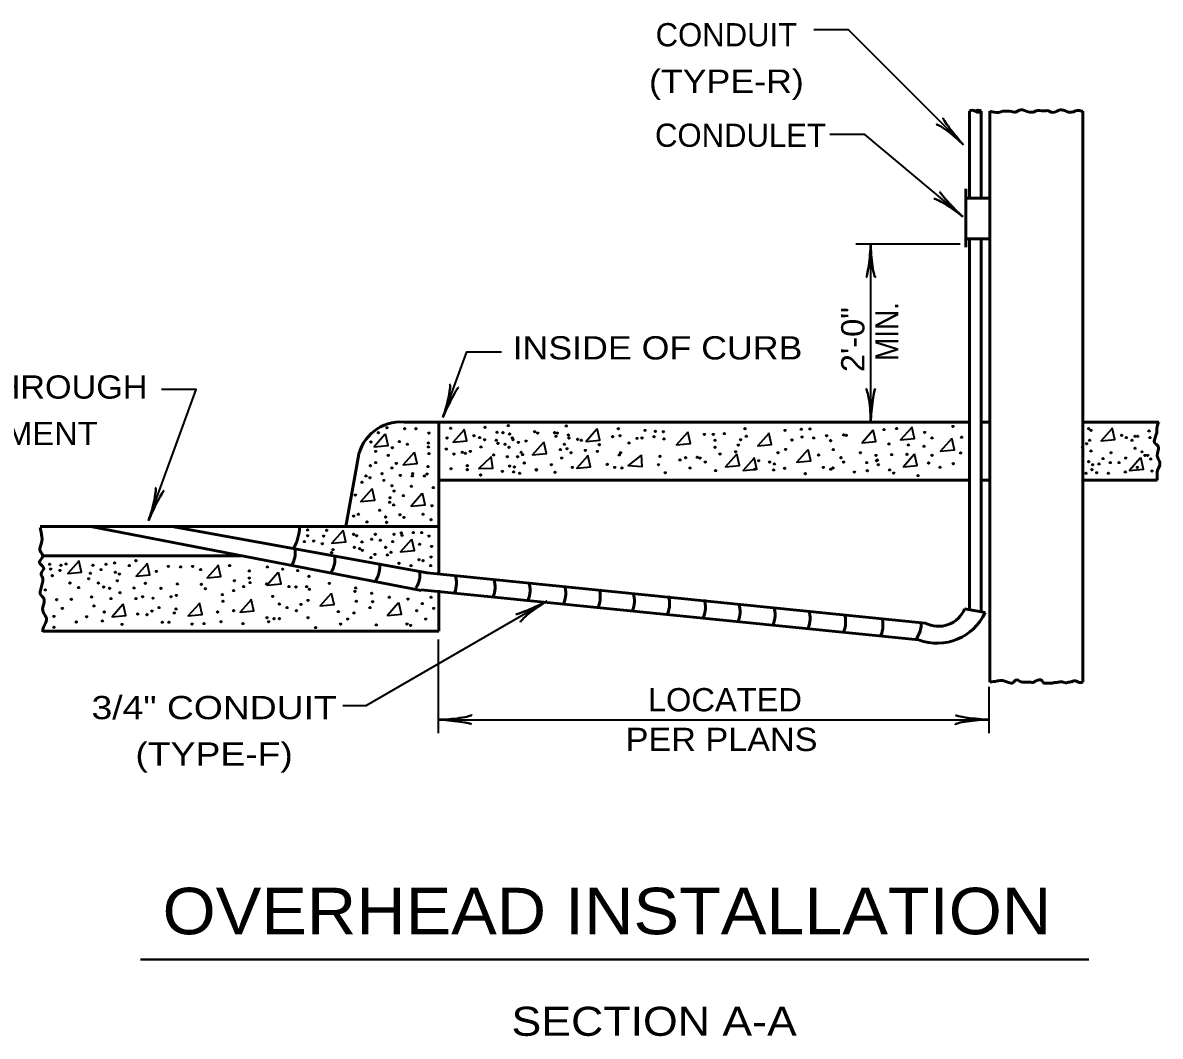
# Model space of a CAD drawing. Extents: x -58 to 622, y -372 to 68.
# Drawn here: x 118 to 215.9, y -96.7 to -9.5 of the extents above; entities that cross this region are included whole.
import ezdxf
from ezdxf.enums import TextEntityAlignment as Align

# ---------------------------------------------------------------- set-up
doc = ezdxf.new("R2010")
doc.units = 0
doc.header["$LTSCALE"] = 0.8
doc.layers.add('1', color=7, linetype='Continuous', lineweight=35)

msp = doc.modelspace()

# ---------------------------------------------------------------- linework, layer by layer
at = {"layer": '1', "lineweight": 53}
for p, q in [((199.5023, -24.5454), (199.5023, -17.0762)), ((200.5023, -24.5244), (200.5023, -17.0762)), ((201.2523, -66.201), (201.2523, -17.0762)), ((209.2523, -66.201), (209.2523, -17.0762)), ((199.1939, -23.7608), (199.1939, -28.7608)), ((199.2202, -24.5454), (199.5083, -24.5454)), ((199.5083, -24.5454), (201.2523, -24.5454)), ((199.5023, -59.9576), (199.5023, -28.0425)), ((200.5023, -60.1339), (200.5023, -28.0425)), ((199.5023, -43.8166), (150.8137, -43.8166)), ((153.8137, -43.8166), (153.8137, -56.8222)), ((201.2523, -43.8166), (200.5175, -43.8166)), ((215.8137, -43.8166), (209.1953, -43.8166)), ((145.8137, -52.8166), (146.8556, -46.9078)), ((199.5023, -48.8166), (153.8137, -48.8166)), ((201.2523, -48.8166), (200.5175, -48.8166)), ((215.6602, -48.8166), (209.2523, -48.8166)), ((153.8137, -52.8166), (119.4935, -52.8166)), ((123.8137, -52.8166), (152.2946, -58.2973)), ((130.8137, -52.8166), (152.8137, -56.8038)), ((119.7456, -55.3166), (136.805, -55.3166)), ((152.8137, -56.8038), (195.6844, -61.108)), ((152.2983, -58.2597), (195.115, -62.5583)), ((153.8137, -58.2809), (153.8137, -61.8166)), ((199.0793, -59.883), (200.8487, -60.195)), ((153.8137, -61.8166), (119.7177, -61.8166))]:
    msp.add_line(p, q, dxfattribs=at)
at = {"layer": '1'}
for p, q in [((198.7092, -28.4962), (189.7092, -28.4962)), ((190.9945, -43.8166), (190.9945, -28.4962)), ((153.7517, -62.5142), (153.7517, -70.593)), ((201.167, -66.593), (201.167, -70.593)), ((153.7517, -69.4262), (201.1672, -69.4262))]:
    msp.add_line(p, q, dxfattribs=at)
at = {"layer": '1', "lineweight": 40}
msp.add_line((128.1151, -90.0752), (209.7699, -90.0752), dxfattribs=at)
at = {"layer": '1'}
for points in [[(198.9823, -19.9613), (189.0828, -10.0618), (186.0828, -10.0618)], [(198.9141, -26.1397), (190.4876, -19.069), (187.4876, -19.069)], [(154.1624, -43.4171), (156.2145, -37.7789), (159.2145, -37.7789)], [(128.8216, -52.2943), (132.9258, -41.018), (129.9258, -41.018)], [(149.1725, -44.9017), (148.2512, -45.9382), (149.4412, -45.8231), (149.2108, -44.825)], [(155.9672, -44.5178), (155.0458, -45.5543), (156.2358, -45.4392), (156.0055, -44.4411)], [(167.4068, -44.4411), (166.4855, -45.4776), (167.6755, -45.3624), (167.4452, -44.3643)], [(175.1996, -44.7482), (174.2782, -45.7847), (175.4682, -45.6695), (175.2379, -44.6714)], [(182.1863, -44.8249), (181.2649, -45.8614), (182.4549, -45.7462), (182.2246, -44.7482)], [(191.169, -44.5562), (190.2477, -45.5927), (191.4377, -45.4776), (191.2073, -44.4795)], [(194.4926, -44.3167), (193.5712, -45.3532), (194.7612, -45.238), (194.5309, -44.2399)], [(211.7451, -44.4027), (210.8237, -45.4392), (212.0137, -45.324), (211.7834, -44.3259)], [(162.8003, -45.5927), (161.8789, -46.6292), (163.0689, -46.5141), (162.8386, -45.516)], [(197.9359, -45.2748), (197.0146, -46.3113), (198.2046, -46.1962), (197.9742, -45.1981)], [(151.6677, -46.4756), (150.7463, -47.5121), (151.9363, -47.3969), (151.706, -46.3988)], [(158.2607, -46.8574), (157.2525, -47.8097), (158.448, -47.7987), (158.3055, -46.7843)], [(166.6007, -46.7443), (165.6793, -47.7808), (166.8693, -47.6657), (166.639, -46.6676)], [(171.2086, -46.6964), (170.1213, -47.5572), (171.3132, -47.6504), (171.2596, -46.6275)], [(179.4222, -46.6292), (178.5009, -47.6657), (179.6909, -47.5505), (179.4606, -46.5524)], [(180.9244, -46.9531), (180.0031, -47.9896), (181.1931, -47.8744), (180.9627, -46.8763)], [(185.5643, -46.2453), (184.643, -47.2818), (185.833, -47.1667), (185.6027, -46.1686)], [(194.7322, -46.6223), (193.8108, -47.6587), (195.0008, -47.5436), (194.7705, -46.5455)], [(214.2019, -46.9363), (213.2806, -47.9728), (214.4706, -47.8577), (214.2403, -46.8596)], [(148.0208, -49.6234), (147.0995, -50.6599), (148.2895, -50.5448), (148.0592, -49.5467)], [(152.3587, -50.0073), (151.4373, -51.0438), (152.6273, -50.9287), (152.397, -49.9306)], [(145.5256, -53.1935), (144.6043, -54.23), (145.7943, -54.1148), (145.5639, -53.1167)], [(151.4373, -53.9613), (150.516, -54.9978), (151.706, -54.8827), (151.4757, -53.8846)], [(122.7816, -55.818), (121.8602, -56.8545), (123.0502, -56.7393), (122.8199, -55.7413)], [(128.6732, -56.0343), (127.7519, -57.0707), (128.9419, -56.9556), (128.7116, -55.9575)], [(134.7769, -56.1878), (133.8556, -57.2243), (135.0456, -57.1092), (134.8152, -56.1111)], [(139.9593, -56.802), (139.038, -57.8385), (140.228, -57.7233), (139.9977, -56.7252)], [(144.5275, -58.6062), (143.6062, -59.6427), (144.7962, -59.5276), (144.5658, -58.5295)], [(126.6003, -59.5276), (125.6789, -60.5641), (126.8689, -60.4489), (126.6386, -59.4508)], [(133.1647, -59.4508), (132.2433, -60.4873), (133.4333, -60.3722), (133.203, -59.3741)], [(137.6177, -59.1437), (136.6963, -60.1802), (137.8863, -60.065), (137.656, -59.0669)], [(163.1207, -59.2342), (147.5323, -68.2342), (145.5323, -68.2342)], [(150.3241, -59.4124), (149.4027, -60.4489), (150.5927, -60.3337), (150.3624, -59.3357)]]:
    msp.add_lwpolyline(points, dxfattribs=at)
at = {"layer": '1', "lineweight": 53}
msp.add_lwpolyline([(199.2202, -28.0454), (200.4964, -28.0454), (201.2523, -28.0454)], dxfattribs=at)
at = {"layer": '1'}
for centre in [(159.7869, -44.1143), (148.6159, -44.7286), (149.3453, -44.3063), (150.8808, -44.3831), (151.8406, -44.3831), (152.9538, -44.767), (154.8348, -44.3447), (156.831, -44.9973), (157.7907, -44.2679), (158.8272, -44.6902), (159.3262, -44.7286), (159.9021, -44.8438), (162.0518, -44.6518), (162.3206, -44.767), (163.7793, -44.7286), (163.8945, -45.0357), (164.0097, -44.767), (164.7774, -44.1527), (164.9693, -44.9205), (168.7697, -45.0741), (169.2688, -44.3831), (169.4223, -44.9973), (171.5721, -44.5367), (172.3398, -45.0741), (172.455, -44.6134), (173.146, -44.6518), (176.6777, -44.8822), (177.4455, -44.8822), (178.4052, -44.8053), (180.171, -44.3831), (180.2862, -45.0357), (183.6259, -44.5367), (185.015, -44.4354), (185.7635, -44.4054), (187.196, -44.9973), (188.6548, -44.9205), (188.8851, -44.9589), (192.1481, -44.4598), (193.219, -44.3755), (195.6442, -44.7048), (198.0696, -44.1958), (209.7682, -44.3832), (209.9601, -44.5367), (212.6089, -44.9589), (213.7605, -45.0358), (213.9908, -45.0358), (214.9506, -44.5751), (147.9633, -45.5347), (149.806, -46.0338), (150.4202, -45.4963), (151.1112, -45.7267), (152.9154, -45.6115), (152.9154, -45.957), (154.5277, -45.1893), (157.3301, -45.1508), (157.4452, -45.957), (157.7524, -45.3427), (158.7505, -45.3812), (158.904, -45.6499), (159.5182, -45.7267), (159.8637, -45.9954), (160.1324, -45.1893), (160.2092, -45.3427), (160.6698, -45.5731), (161.3225, -45.4579), (164.6238, -45.7267), (165.0077, -45.1893), (165.7755, -45.3044), (166.0826, -45.3812), (167.6181, -45.7651), (170.1901, -45.6115), (170.8811, -45.2276), (171.3033, -45.1893), (173.1844, -45.266), (177.599, -45.3812), (177.599, -45.9954), (179.5952, -45.8034), (179.7872, -45.3427), (184.2066, -45.3636), (185.0847, -45.1125), (186.0929, -45.1839), (187.5415, -45.4196), (192.5602, -45.6929), (194.237, -45.7828), (195.5844, -45.9025), (196.2731, -45.1839), (198.8181, -45.1241), (209.2308, -45.9954), (209.5762, -45.6883), (209.8449, -45.3813), (212.9928, -45.1509), (213.4918, -45.3813), (213.7605, -46.0722), (215.0273, -45.1509), (148.3857, -46.3409), (149.4605, -46.6864), (152.9538, -46.5328), (154.4509, -46.149), (155.1035, -46.5712), (155.8329, -46.4177), (156.1017, -46.4944), (156.5239, -46.3409), (158.5202, -46.648), (159.7102, -46.8015), (160.5931, -46.8015), (160.9002, -46.4177), (161.0153, -46.6096), (164.2783, -46.1873), (164.3935, -46.9167), (164.8542, -46.1106), (165.1997, -46.4561), (166.4281, -46.2641), (167.4646, -46.3409), (169.3456, -46.648), (169.4607, -46.4561), (172.8389, -46.7632), (175.0654, -46.8783), (176.0635, -46.8399), (176.2938, -46.9167), (178.0212, -46.5712), (179.3648, -46.3792), (183.0118, -46.4561), (183.6676, -46.172), (186.5121, -46.6511), (187.7718, -46.1873), (188.4245, -46.8783), (190.1135, -46.4561), (191.4571, -46.6863), (192.8007, -46.6096), (194.1172, -46.5912), (196.2731, -46.681), (198.7283, -46.4714), (209.9601, -46.3025), (210.9966, -46.9552), (211.6876, -46.4561), (212.9544, -46.9168), (214.3363, -46.3793), (214.6051, -46.6864), (214.8354, -46.6864), (215.1041, -46.9935), (147.925, -47.5693), (148.3857, -47.3006), (149.7676, -47.7612), (150.1515, -47.3774), (152.877, -47.6461), (154.8732, -47.838), (156.2552, -47.5693), (156.2552, -47.9148), (159.9021, -47.6077), (160.3244, -47.6845), (161.1689, -47.339), (162.2054, -47.9147), (162.2054, -47.9532), (163.5106, -47.4925), (165.3148, -47.7228), (168.3091, -47.4542), (168.9617, -47.7228), (169.5759, -47.7612), (172.7237, -47.4925), (174.5663, -47.0703), (175.4493, -47.7612), (176.7545, -47.2622), (177.6374, -47.9916), (181.0156, -47.8764), (181.3611, -47.147), (182.2823, -47.2622), (182.6496, -47.9386), (182.7047, -47.4157), (183.5876, -47.7996), (186.9273, -47.7228), (187.56, -47.8787), (187.7335, -47.7612), (188.6548, -47.2622), (190.651, -47.3006), (190.7039, -47.9984), (191.4955, -47.147), (191.5722, -47.0703), (191.6491, -47.4925), (192.6202, -47.9386), (195.9737, -47.3397), (196.9617, -47.699), (198.0995, -47.3996), (209.7682, -47.2238), (210.0369, -47.9148), (210.1137, -47.4926), (210.6511, -47.4157), (211.6108, -47.3006), (212.3786, -47.3006), (213.9525, -47.7229), (215.2192, -48.03), (147.1956, -48.9897), (147.5411, -48.4522), (147.8866, -48.6058), (148.9231, -48.2603), (149.0766, -48.8362), (150.497, -48.4138), (151.5334, -48.4522), (151.5718, -48.2603), (152.5699, -48.4522), (152.8003, -48.2987), (157.4068, -48.3755), (159.2879, -48.0683), (160.2476, -48.1067), (160.785, -48.2219), (163.8177, -48.1451), (173.2996, -48.1835), (185.3534, -48.2602), (189.5961, -48.1182), (192.9795, -48.2081), (195.0754, -48.4177), (209.5378, -48.2219), (210.4592, -48.1836), (211.4572, -48.2219), (212.916, -48.1067), (149.7676, -49.2967), (149.9595, -49.7574), (151.4567, -49.3352), (153.3377, -49.4503), (146.6197, -50.1029), (149.5757, -50.7172), (149.6141, -50.3332), (149.9212, -50.9475), (150.7657, -50.1413), (146.4663, -51.9072), (146.8885, -51.7536), (148.7311, -51.4082), (150.4586, -51.792), (152.4547, -51.7536), (153.2225, -51.0242), (147.6178, -52.4062), (149.2302, -51.9839), (149.3069, -52.4446), (150.8041, -52.0223), (153.1457, -52.2142), (142.5122, -53.0972), (142.5122, -53.5962), (143.8942, -53.6347), (144.1629, -53.1356), (146.4663, -53.4811), (146.7349, -53.5962), (148.0402, -53.9033), (148.3473, -53.4811), (149.9595, -53.4811), (150.5737, -53.3659), (150.6505, -53.5578), (151.6103, -53.3275), (152.3396, -53.3275), (152.9538, -53.6347), (142.2435, -54.0953), (143.0497, -54.0569), (143.7791, -54.2873), (144.7003, -54.7862), (146.543, -54.5943), (147.0037, -54.7095), (147.1956, -54.1337), (147.234, -54.8631), (148.7695, -53.9802), (149.2302, -54.5943), (149.8443, -54.0953), (152.1477, -54.3257), (153.1842, -54.5176), (127.7328, -55.746), (144.5852, -55.055), (147.9633, -55.4772), (148.3088, -55.2086), (149.3837, -55.2469), (149.6908, -55.0166), (152.1093, -55.6692), (152.4547, -55.746), (153.1457, -55.4389), (120.3167, -56.0487), (120.4066, -56.4678), (121.185, -56.5876), (121.2747, -56.1385), (121.7239, -56.0187), (123.8197, -56.8271), (124.0292, -56.1385), (124.7386, -56.5138), (125.1608, -56.0532), (125.8902, -55.938), (125.967, -56.7442), (127.157, -56.1683), (129.4987, -56.6673), (130.5352, -56.2451), (131.5717, -56.2835), (132.6082, -56.2451), (133.2992, -56.5138), (135.7943, -56.1683), (137.4834, -56.629), (139.0573, -56.2835), (140.3625, -56.4754), (141.6677, -56.5906), (150.3818, -55.9763), (151.4183, -56.1683), (153.1073, -56.1683), (120.5263, -57.0367), (122.0532, -57.6654), (123.6699, -57.3061), (124.5082, -57.6654), (126.1206, -57.4735), (126.3125, -56.8977), (128.5501, -57.6953), (131.3029, -57.7422), (133.3759, -57.7806), (136.2166, -57.4735), (137.4834, -57.2432), (137.5602, -57.6271), (138.9806, -57.7422), (142.6274, -57.0896), (144.3932, -57.7038), (119.9275, -58.2642), (122.8017, -58.0546), (124.9689, -58.0109), (125.4679, -58.1261), (126.3645, -58.5037), (127.5793, -58.0877), (129.8826, -58.1261), (131.2262, -58.7403), (133.7214, -58.1645), (135.1802, -58.6635), (136.1398, -58.3181), (137.0228, -57.9726), (139.518, -58.8171), (140.9, -57.9726), (141.5142, -58.0109), (142.4355, -57.9726), (142.6658, -58.2029), (146.5814, -58.3948), (146.6582, -58.0877), (148.0402, -58.5483), (120.9155, -59.1025), (122.173, -59.0726), (123.9095, -58.863), (124.1191, -59.6414), (125.5831, -59.009), (127.7328, -59.009), (128.3087, -58.8555), (129.1916, -58.9707), (129.729, -59.7767), (130.7655, -58.8555), (135.2185, -59.2393), (140.0938, -59.4697), (140.7464, -59.7767), (141.9364, -59.5081), (142.5507, -59.1626), (146.6966, -59.2393), (147.8866, -59.7767), (148.1169, -59.2777), (149.5373, -58.8938), (151.1496, -59.0474), (152.378, -59.4313), (153.1457, -58.8938), (120.676, -60.5396), (121.3946, -59.851), (123.4903, -60.5695), (125.0073, -60.1607), (127.8914, -60.33), (128.6926, -60.391), (129.1148, -60.0839), (131.0342, -60.2374), (131.1877, -59.8919), (134.7578, -60.1607), (136.1398, -60.0455), (139.0189, -60.6597), (139.6332, -60.7365), (140.0938, -60.7365), (141.5526, -60.0455), (142.5507, -60.6597), (145.1611, -60.1223), (145.9672, -60.7749), (146.5047, -60.2374), (151.9173, -60.0455), (152.6851, -60.7749), (153.3761, -59.8536), (120.676, -61.4677), (122.5922, -61.0186), (124.8537, -60.9284), (126.5428, -61.2355), (129.9977, -61.0436), (130.5736, -61.0436), (132.5697, -61.1972), (133.6062, -61.1587), (135.065, -61.0052), (136.946, -61.1587), (139.1725, -61.0052), (143.2032, -61.5042), (145.353, -61.1972), (148.424, -61.2739), (151.0728, -61.1972), (151.3799, -61.3123)]:
    msp.add_circle(centre, 0.0607, dxfattribs=at)
at = {"layer": '1', "lineweight": 53}
for centre, radius, start, end in [((199.7498, -17.3906), 0.4001, 51.28288, 128.19904), ((200.2502, -17.3906), 0.4001, 51.80096, 128.71712), ((200.2502, -16.7662), 0.4001, 231.28288, 308.19904), ((150.5255, -47.5272), 3.7218, 85.55938, 170.41856), ((138.0774, -52.8064), 3.7363, 329.7014, 359.8431), ((139.2853, -54.9951), 2.1707, 327.00343, 7.84739), ((142.7018, -55.5709), 2.1707, 327.00343, 7.84739), ((146.5544, -56.2619), 2.1707, 327.00343, 7.84739), ((150.0185, -56.8976), 2.1707, 327.00343, 7.84739), ((153.1665, -57.6512), 2.1707, 337.00343, 17.84739), ((156.4868, -58.0188), 2.1707, 337.00343, 17.84739), ((159.508, -58.2831), 2.1707, 337.00343, 17.84739), ((162.5673, -58.5508), 2.1707, 337.00343, 17.84739), ((165.5468, -58.85), 2.1707, 337.00343, 17.84739), ((168.4814, -59.2224), 2.1707, 337.00343, 17.84739), ((171.5059, -59.4484), 2.1707, 337.00343, 17.84739), ((174.6001, -59.7577), 2.1707, 337.00343, 17.84739), ((177.5729, -60.1334), 2.1707, 337.00343, 17.84739), ((180.5941, -60.3977), 2.1707, 337.00343, 17.84739), ((183.6119, -60.7003), 2.1707, 337.00343, 17.84739), ((186.6679, -61.0061), 2.1707, 337.00343, 17.84739), ((189.8769, -61.3254), 2.1707, 337.00343, 17.84739), ((196.7237, -58.3241), 4.5295, 249.19696, 335.60393), ((196.8228, -58.946), 2.4434, 242.23273, 337.44956), ((193.1718, -61.1685), 2.1707, 322.00343, 2.84739)]:
    msp.add_arc(centre, radius, start, end, dxfattribs=at)
at = {"layer": '1', "lineweight": 40}
for centre, major_axis, ratio, start_param, end_param in [((198.0154, -19.3851), (1.3731, -1.1523), 0.122415, 0.8963533, 3.1415927), ((198.3396, -19.0194), (1.1178, -1.3662), 0.07063, 3.1407148, 5.41811), ((198.1917, -25.2573), (1.2326, -1.2636), 0.07063, 3.1407148, 5.41811), ((197.9006, -25.6499), (1.4683, -1.0282), 0.122415, 0.8963533, 3.1415927), ((190.7829, -29.6168), (-0.1757, -1.7565), 0.07063, 6.2823074, 8.5597026), ((190.7829, -29.6168), (-0.1757, -1.7565), 0.07063, 6.2823074, 8.5597026), ((191.2708, -29.5874), (-0.1562, 1.7857), 0.122415, 0.8963533, 3.1415927), ((191.2708, -29.5874), (-0.1562, 1.7857), 0.122415, 0.8963533, 3.1415927), ((154.276, -42.2972), (-0.464, -1.7314), 0.122415, 0.8963533, 3.1415927), ((154.276, -42.2972), (-0.464, -1.7314), 0.122415, 0.8963533, 3.1415927), ((154.7445, -42.4365), (0.7658, 1.5905), 0.07063, 6.2823074, 8.5597026), ((154.7445, -42.4365), (0.7658, 1.5905), 0.07063, 6.2823074, 8.5597026), ((190.7182, -42.7254), (0.1562, -1.7857), 0.122415, 0.8963533, 3.1415927), ((190.7182, -42.7254), (0.1562, -1.7857), 0.122415, 0.8963533, 3.1415927), ((191.2061, -42.6961), (0.1757, 1.7565), 0.07063, 6.2823074, 8.5597026), ((191.2061, -42.6961), (0.1757, 1.7565), 0.07063, 6.2823074, 8.5597026), ((128.9352, -51.1744), (-0.464, -1.7314), 0.122415, 0.8963533, 3.1415927), ((128.9352, -51.1744), (-0.464, -1.7314), 0.122415, 0.8963533, 3.1415927), ((129.4037, -51.3138), (0.7658, 1.5904), 0.07063, 6.2823074, 8.5597026), ((129.4037, -51.3138), (0.7658, 1.5904), 0.07063, 6.2823074, 8.5597026), ((162.0446, -59.6112), (1.609, 0.7261), 0.07063, 3.1407148, 5.41811), ((162.0446, -59.6112), (1.609, 0.7261), 0.07063, 3.1407148, 5.41811), ((162.3139, -60.0191), (1.4684, 1.0281), 0.122415, 0.8963533, 3.1415927), ((162.3139, -60.0191), (1.4684, 1.0281), 0.122415, 0.8963533, 3.1415927), ((154.8723, -69.6378), (1.7565, -0.1757), 0.07063, 6.2823074, 8.5597026), ((154.8429, -69.1499), (-1.7857, -0.1562), 0.122415, 0.8963533, 3.1415927), ((200.076, -69.7025), (1.7857, 0.1562), 0.122415, 0.8963533, 3.1415927), ((200.0467, -69.2146), (1.7565, -0.1757), 0.07063, 3.1407148, 5.41811)]:
    msp.add_ellipse(centre, major_axis=major_axis, ratio=ratio, start_param=start_param, end_param=end_param, dxfattribs=at)
at = {"layer": '1', "lineweight": 53}
for points in [[(201.2523, -17.0762), (202.0042, -17.1688), (202.3784, -17.079), (203.1119, -17.1089), (203.576, -17.1089), (203.7856, -16.9742), (204.3844, -17.064), (204.9982, -17.1389), (205.2378, -17.0341), (205.8515, -17.0491), (206.2856, -17.0341), (206.5401, -17.1538), (207.0342, -17.064), (207.1389, -17.0042), (207.4982, -16.9742), (207.6778, -17.0191), (208.0222, -17.1389), (208.5761, -17.079), (208.7558, -17.0191), (209.0551, -17.0341), (209.2523, -17.0762)], [(215.8137, -43.8166), (215.6602, -44.192), (215.5835, -44.8829), (215.43, -45.5739), (215.7371, -45.881), (215.6602, -46.7256), (215.8906, -47.3397), (215.6602, -48.1075), (215.6602, -48.6449), (215.6602, -48.822)], [(119.5024, -52.8765), (119.5642, -53.2926), (119.6409, -54.0603), (119.4873, -54.5977), (119.4873, -54.9048), (119.7177, -55.3655), (119.4106, -55.9029), (119.7944, -56.3636), (119.5642, -56.901), (119.7177, -57.2848), (119.7177, -57.5152), (119.4873, -58.4365), (119.4873, -58.5901), (119.7944, -58.9739), (119.7177, -59.7417), (119.7944, -60.2791), (120.0247, -60.663), (119.8712, -61.2772), (119.7177, -61.6611), (119.7177, -61.8765)], [(201.2523, -66.201), (201.8918, -66.0967), (202.3409, -66.0517), (203.2841, -66.2164), (203.4638, -66.0218), (203.9427, -66.1566), (204.332, -66.2015), (204.6912, -66.2015), (205.0356, -66.2015), (205.1553, -66.1267), (205.7392, -66.0517), (205.859, -66.2464), (206.1583, -66.2913), (206.6075, -66.2763), (206.8919, -66.2164), (207.0267, -66.2164), (207.371, -66.1715), (207.7602, -66.2464), (208.1045, -66.1865), (208.2692, -66.1566), (208.5087, -66.0817), (208.7632, -66.1416), (209.0177, -66.2314), (209.2523, -66.201)]]:
    msp.add_spline(points, degree=3, dxfattribs=at)

# ---------------------------------------------------------------- texts
at = {"layer": '1'}
msp.add_text('CONDUIT', height=2, dxfattribs=at).set_placement((178.5693, -11.4893), align=Align.CENTER)
for s, width, p in [('(TYPE-R)', 1.15, (178.5693, -15.4893)), ('DRILL THROUGH', 1.1, (116.7143, -41.8023)), ('PAVEMENT', 1.05, (116.7143, -45.8023)), ('3/4" CONDUIT', 1.2, (134.4652, -69.3843)), ('(TYPE-F)', 1.2, (134.4653, -73.3843))]:
    msp.add_text(s, height=2, dxfattribs=dict(at, width=width)).set_placement(p, align=Align.CENTER)
msp.add_text('CONDULET', height=2, dxfattribs=at).set_placement((172.4247, -20.1359))
for s, width, p in [('2\'-0"', 1.05, (190.4483, -39.5212)), ('MIN.', 0.9, (193.3841, -38.5653))]:
    msp.add_text(s, height=2, rotation=90, dxfattribs=dict(at, width=width)).set_placement(p)
for s, height, width, p in [('INSIDE OF CURB', 2, 1.15, (160.1649, -38.4319)), ('LOCATED', 2, 1.05, (171.8098, -68.7078)), ('PER PLANS', 2, 1.1, (169.8982, -72.1213)), ('OVERHEAD INSTALLATION', 4, 1.1, (130.0267, -87.8905)), ('SECTION A-A', 2.5, 1.15, (160.0668, -96.6295))]:
    msp.add_text(s, height=height, dxfattribs=dict(at, width=width)).set_placement(p)

doc.saveas('drawing.dxf')
